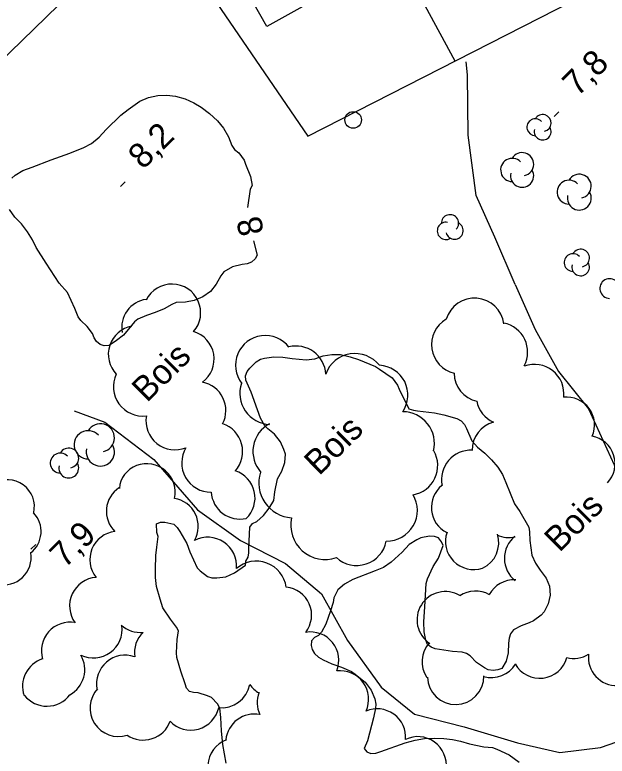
# Model space of a CAD drawing. Extents: x 381879 to 384696, y 5564785 to 5567594.
# Drawn here: x 382944.6 to 383016.3, y 5565699.1 to 5565788.8 of the extents above; entities that cross this region are included whole.
import ezdxf

# ---------------------------------------------------------------- set-up
doc = ezdxf.new("R2010")
doc.units = 0
for name, color, linetype in [('Niveau 2', 7, 'Continuous'), ('Niveau 21', 7, 'Continuous'), ('Niveau 22', 7, 'Continuous'), ('Niveau 3', 7, 'Continuous'), ('Niveau 31', 7, 'Continuous'), ('Niveau 36', 7, 'Continuous'), ('Niveau 41', 7, 'Continuous'), ('Niveau 44', 7, 'Continuous')]:
    doc.layers.add(name, color=color, linetype=linetype)

msp = doc.modelspace()

# ---------------------------------------------------------------- linework, layer by layer
at = {"layer": 'Niveau 2'}
for points in [[(382944.26, 5565769.03), (382944.69, 5565769.41), (382945.61, 5565769.97), (382946.74, 5565770.36), (382949.01, 5565771.25), (382951.29, 5565772.07), (382952.98, 5565772.77), (382953.92, 5565773.25), (382954.82, 5565774.02), (382955.69, 5565774.92), (382957.44, 5565776.67), (382958.34, 5565777.37), (382959.77, 5565778.35), (382960.82, 5565778.79), (382961.91, 5565779.05), (382963.03, 5565779.1), (382964.07, 5565778.96), (382965.22, 5565778.66), (382966.29, 5565778.18), (382967.16, 5565777.65), (382968.19, 5565776.85), (382969.13, 5565775.97), (382969.88, 5565775.09), (382970.47, 5565774.06), (382970.87, 5565772.98), (382971.22, 5565772.52), (382971.71, 5565772.13), (382972.35, 5565771.24), (382972.53, 5565770.73), (382973.12, 5565769.26), (382973.33, 5565768.16), (382973.1, 5565767.71), (382972.79, 5565765.52)], [(382950, 5565756.35), (382948.41, 5565758.77), (382947.21, 5565760.67), (382946.78, 5565761.6), (382946.18, 5565762.57), (382945.43, 5565763.51), (382944.65, 5565764.35), (382943.99, 5565765.27)], [(382973.5, 5565761.48), (382973.93, 5565759.75), (382973.71, 5565759.3), (382973.27, 5565758.9), (382972.72, 5565758.69), (382972.13, 5565758.61), (382970.94, 5565758.34), (382969.91, 5565757.71), (382969.55, 5565757.22), (382968.98, 5565756.22), (382968.3, 5565755.33), (382967.39, 5565754.71), (382966.34, 5565754.24), (382965.27, 5565754.04), (382964.15, 5565753.99), (382963.64, 5565753.78), (382962.68, 5565753.25), (382961.59, 5565752.79), (382960.57, 5565752.44), (382959.53, 5565751.99), (382959.12, 5565751.67), (382958.76, 5565751.23), (382957.78, 5565750.05), (382956.92, 5565749.42), (382956.03, 5565748.8), (382955.43, 5565748.75), (382954.96, 5565748.93), (382954.53, 5565749.29), (382954.21, 5565749.75), (382954.03, 5565750.25), (382953.4, 5565751.1), (382952.6, 5565751.82), (382952.3, 5565752.29), (382951.88, 5565753.3), (382950.99, 5565755.2), (382950, 5565756.35)], [(382961.97, 5565725.69), (382961.82, 5565726.2), (382961.76, 5565727.22), (382962.25, 5565727.45), (382962.78, 5565727.44), (382963.86, 5565727.19), (382964.28, 5565726.79), (382964.58, 5565726.32), (382965.43, 5565724.87), (382965.81, 5565723.84), (382966.67, 5565721.9), (382967.03, 5565721.55), (382967.94, 5565720.88), (382968.47, 5565720.69), (382969.08, 5565720.69), (382970.15, 5565720.83), (382971.19, 5565721.32), (382972.55, 5565722.22), (382972.59, 5565722.73), (382972.84, 5565723.2), (382972.95, 5565723.74), (382972.94, 5565724.29), (382973.04, 5565726.84), (382973.39, 5565727.28), (382973.9, 5565727.54), (382974.72, 5565728.26), (382975.39, 5565729.13), (382975.94, 5565730.07), (382976.09, 5565731.09), (382976.4, 5565732.69), (382976.91, 5565733.62), (382977.27, 5565734.64), (382977.36, 5565735.68), (382977.18, 5565736.23), (382976.77, 5565737.16), (382976.04, 5565738.08), (382975.22, 5565738.71), (382974.86, 5565739.09), (382974.36, 5565740.01), (382974, 5565741.04), (382973.21, 5565743.18), (382972.57, 5565744.62), (382972.54, 5565745.13), (382972.74, 5565745.67), (382973.05, 5565746.07), (382973.82, 5565746.83), (382974.34, 5565747.15), (382974.84, 5565747.29), (382975.95, 5565747.44), (382977.06, 5565747.4), (382978.16, 5565747.24), (382979.86, 5565747.08), (382980.9, 5565747.18), (382981.92, 5565747.54), (382982.97, 5565747.73), (382984, 5565747.72), (382985.2, 5565747.45), (382986.18, 5565747.1), (382988.25, 5565746.28), (382988.73, 5565745.94), (382990.27, 5565744.91), (382990.93, 5565744.01), (382991.11, 5565743.51), (382992.3, 5565741.13), (382992.84, 5565740.97), (382993.34, 5565740.92), (382995.4, 5565740.66), (382996.5, 5565740.42), (382998.1, 5565739.98), (382998.6, 5565739.69)], [(382998.6, 5565739.69), (382999.03, 5565739.26), (382999.24, 5565738.76), (382999.92, 5565737.29), (383000.59, 5565736.52), (383001.47, 5565735.77), (383002.27, 5565734.97), (383003.03, 5565734.08), (383003.6, 5565733.2), (383004.01, 5565732.23), (383005.07, 5565729.66), (383005.7, 5565728.72), (383006.8, 5565726.85), (383006.88, 5565726.29), (383006.9, 5565725.23), (383007.15, 5565723.43), (383007.59, 5565722.48), (383008.17, 5565721.62), (383008.9, 5565720.66), (383009.31, 5565719.68), (383009.39, 5565718.61), (383009.14, 5565717.55), (383008.67, 5565716.59), (383008.27, 5565716.19), (383007.36, 5565715.5), (383006.84, 5565715.26), (383005.86, 5565714.9), (383004.95, 5565714.41), (383004.59, 5565713.92), (383004.41, 5565713.41), (383004.33, 5565712.8), (383004.3, 5565711.62), (383004.07, 5565710.61), (383003.53, 5565709.75), (383003.05, 5565709.57), (383002.5, 5565709.48), (383001.88, 5565709.57), (383001.42, 5565709.82), (383000.45, 5565710.47), (382999.7, 5565711.27), (382999.27, 5565711.54), (382998.74, 5565711.71), (382997.58, 5565711.79), (382995.48, 5565712.1), (382994.99, 5565712.33), (382994.56, 5565712.66), (382994.32, 5565713.17), (382994.14, 5565714.19), (382994.11, 5565715.39), (382994.2, 5565717.18), (382994.36, 5565720.03), (382994.54, 5565720.58), (382995.22, 5565722.09), (382995.88, 5565723.08), (382996.45, 5565724.6), (382996.24, 5565725.07), (382995.86, 5565725.54), (382995.37, 5565725.71), (382994.77, 5565725.75), (382993.75, 5565725.56), (382993.24, 5565725.32), (382992.31, 5565724.72), (382991.47, 5565723.83), (382990.16, 5565722.62), (382989.22, 5565721.96), (382988.21, 5565721.56), (382985.53, 5565720.5), (382984.51, 5565719.95), (382983.7, 5565719.25), (382983.22, 5565718.3), (382983.13, 5565717.74), (382982.81, 5565716.71), (382982.25, 5565715.09), (382981.74, 5565714.13), (382981.34, 5565713.73), (382980.87, 5565713.47), (382980.52, 5565713.1), (382980.47, 5565712.52), (382980.61, 5565712.03), (382980.89, 5565711.57), (382981.35, 5565711.13), (382981.91, 5565710.77), (382982.97, 5565710.29), (382984.16, 5565709.89), (382985.36, 5565709.36), (382985.79, 5565709.05), (382987.01, 5565708.07), (382987.73, 5565707.12), (382988.18, 5565706.06), (382988.3, 5565705.44), (382988.27, 5565704.93), (382988, 5565703.76), (382987.28, 5565701), (382986.87, 5565700.05), (382987.2, 5565699.67), (382987.69, 5565699.44), (382988.31, 5565699.49), (382988.91, 5565699.71), (382991.82, 5565700.75), (382993.03, 5565701.07), (382994.19, 5565701.26)], [(382970.2, 5565698.28), (382969.8, 5565700.53), (382969.61, 5565702.21), (382969.53, 5565703.83), (382969.43, 5565704.94), (382969.16, 5565705.48), (382968.42, 5565706.22), (382967.94, 5565706.42), (382966.8, 5565706.8), (382966.26, 5565706.84), (382965.76, 5565706.97), (382965.41, 5565707.36), (382965.25, 5565707.9), (382964.7, 5565709.42), (382964.21, 5565711.06), (382964.2, 5565711.65), (382964.28, 5565713.25), (382964.44, 5565714.28), (382964.18, 5565714.74), (382963.46, 5565715.7), (382962.55, 5565717.06), (382962.2, 5565718.11), (382961.76, 5565719.64), (382961.65, 5565720.73), (382961.63, 5565721.77), (382961.68, 5565723.39), (382961.81, 5565724.4), (382961.97, 5565725.69)], [(382994.19, 5565701.26), (382995.34, 5565701.31), (382996.53, 5565701.27), (382997.56, 5565701.15), (382998.55, 5565700.95), (382999.64, 5565700.62), (383001.34, 5565700.26), (383002.42, 5565700.18), (383002.92, 5565699.99), (383004.41, 5565699.29), (383005.64, 5565698.42)]]:
    msp.add_lwpolyline(points, dxfattribs=at)
at = {"layer": 'Niveau 21'}
msp.add_lwpolyline([(382914.61, 5565754.3), (382936.73, 5565777.21), (382952.8, 5565792.82), (382963.76, 5565801.52), (382976.97, 5565810.61), (383000.04, 5565824), (383016.43, 5565833.11), (383031.77, 5565840.06), (383045.77, 5565844.63), (383055.95, 5565847.35), (383061.35, 5565847.84), (383065.37, 5565846.21), (383068.45, 5565843.53), (383070.89, 5565839.89)], dxfattribs=at)
at = {"layer": 'Niveau 22'}
for points in [[(383005.14, 5565756.17), (383002.69, 5565761.9), (383000.42, 5565766.95), (382999.46, 5565774.26), (382999.37, 5565781.55), (382999.22, 5565783.11)], [(383005.14, 5565756.17), (383007.58, 5565750.73), (383010.37, 5565745.68), (383014, 5565741.13), (383017.55, 5565733.39), (383021.21, 5565726.5), (383025.43, 5565721.93), (383027.94, 5565717.14), (383028.48, 5565711.52), (383029.32, 5565705.94), (383031.4, 5565700.76), (383032.94, 5565694.87), (383033.8, 5565689.8), (383035.77, 5565686.13), (383037.71, 5565681.07), (383040.42, 5565674.31)], [(382951.83, 5565740.92), (382955.51, 5565739.53), (382961.45, 5565735.01), (382966.72, 5565728.93), (382971.91, 5565725.21), (382977.38, 5565722.44), (382981.72, 5565718.78), (382984.86, 5565713.13), (382988.92, 5565707.48), (382992.95, 5565704.21), (382998.97, 5565702.7), (383005.41, 5565700.75), (383010.56, 5565699.58), (383015.48, 5565700.17), (383021.4, 5565702.26), (383026.37, 5565705.13), (383029.61, 5565709.24), (383032.93, 5565713.08), (383036.81, 5565716), (383040.62, 5565718.42), (383043.54, 5565721.3)]]:
    msp.add_lwpolyline(points, dxfattribs=at)
at = {"layer": 'Niveau 3'}
for p, q in [((383009.87, 5565776.49), (383010.44, 5565777.06)), ((382957.42, 5565768.05), (382957.99, 5565768.62)), ((382946.59, 5565724.17), (382947.16, 5565724.74))]:
    msp.add_line(p, q, dxfattribs=at)
at = {"layer": 'Niveau 31'}
msp.add_lwpolyline([(382971.04, 5565794.61), (382981.13, 5565800.28), (382985.19, 5565793.05), (382975.1, 5565787.38)], close=True, dxfattribs=at)
at = {"layer": 'Niveau 36'}
msp.add_circle((382985.553, 5565776.09), 1, dxfattribs=at)
at = {"layer": 'Niveau 41'}
for points in [[(382997.88, 5565783.22), (382983.61, 5565809.56)], [(382963.3, 5565798.68), (382980.07, 5565774.13), (383042.17, 5565805.84)]]:
    msp.add_lwpolyline(points, dxfattribs=at)
at = {"layer": 'Niveau 44'}
for centre, radius, start, end in [((383008.468, 5565775.714), 1.023, 282.26915, 149.72624), ((383007.589, 5565775.203), 1.023, 44.11535, 269.80394), ((383008.468, 5565774.692), 1.023, 166.93684, 29.62121), ((383005.986, 5565770.738), 1.398, 282.26915, 149.72624), ((383004.783, 5565770.039), 1.398, 44.11535, 269.80394), ((383005.986, 5565769.34), 1.398, 166.93684, 29.62121), ((383012.896, 5565768.083), 1.445, 282.26915, 149.72624), ((383011.654, 5565767.361), 1.445, 44.11535, 269.80394), ((383012.896, 5565766.638), 1.445, 166.93684, 29.62121), ((383013.059, 5565759.38), 1.07, 282.26915, 149.72624), ((383012.139, 5565758.845), 1.07, 44.11535, 269.80394), ((383013.059, 5565758.31), 1.07, 166.93684, 29.62121), ((383016.574, 5565755.7), 1.19, 44.11535, 269.80394), ((383003.085, 5565748.021), 3.566, 332.23791, 78.61323), ((382954.977, 5565737.645), 1.707, 282.26915, 149.72624), ((382968.623, 5565735.975), 3.565, 319.03076, 71.22466), ((382953.51, 5565736.792), 1.707, 44.11535, 269.80394), ((382951.16, 5565735.192), 1.204, 282.26915, 149.72624), ((382954.977, 5565735.938), 1.707, 166.93684, 29.62121), ((382992.228, 5565734.266), 3.552, 279.26271, 30.36342), ((382950.125, 5565734.591), 1.204, 44.11535, 269.80394), ((382951.16, 5565733.989), 1.204, 166.93684, 29.62121), ((382959.12, 5565728.757), 3.414, 123.72138, 225.56115), ((382989.608, 5565728.863), 3.713, 269.10953, 30.7211), ((382985.983, 5565725.829), 3.631, 227.29769, 349.22981), ((382973.827, 5565719.048), 3.673, 8.48236, 130.53076), ((382954.134, 5565714.487), 3.477, 244.23376, 7.46701), ((382949.621, 5565709.612), 3.472, 298.81948, 30.16647), ((383002.265, 5565712.05), 3.406, 254.29453, 328.65221), ((382983.986, 5565706.028), 3.439, 335.29034, 97.11484), ((382948.515, 5565708.65), 3.472, 218.40596, 323.18705)]:
    msp.add_arc(centre, radius, start, end, dxfattribs=at)
for centre, major_axis, ratio, start_param, end_param in [((382997.262, 5565763.587), (0.912, -0.513), 0.999925, 6.029005, 9.968014), ((382996.769, 5565762.67), (0.912, -0.513), 0.999925, 1.88946, 5.776035), ((382997.815, 5565762.706), (0.912, -0.513), 0.999925, 3.902388, 7.872264), ((382963.632, 5565752.767), (-1.545, 3.113), 0.999985, 3.537026, 6.933673), ((382961.033, 5565750.961), (-2.744, -2.124), 0.999985, 4.206476, 5.789984), ((383000.229, 5565750.973), (-3.57, 0.023), 0.999871, 3.274852, 6.005186), ((382998.61, 5565748.925), (-0.823, -3.473), 0.999872, 3.908751, 6.273874), ((382959.408, 5565747.738), (-3.34, 0.945), 0.999408, 5.169945, 7.322225), ((382965.261, 5565747.16), (-1.136, 3.284), 0.999985, 3.445702, 5.659007), ((382974.925, 5565746.414), (1.104, -3.427), 0.999352, 1.908495, 5.055203), ((382978.648, 5565745.149), (-3.267, 1.509), 0.999875, 3.633014, 5.389209), ((382985.772, 5565744.081), (-0.604, 3.709), 0.999624, 5.2197, 7.345321), ((383007.471, 5565742.961), (-2.664, 2.369), 0.999986, 3.749859, 5.788773), ((382988.57, 5565742.816), (-3.594, 0.17), 0.999985, 2.594107, 4.717896), ((382960.114, 5565743.82), (-3.219, -1.511), 0.999892, 5.402374, 7.535196), ((383001.318, 5565745.536), (1.215, -3.35), 0.999986, 4.386078, 5.707066), ((382966.679, 5565740.949), (-1.96, 2.875), 0.999985, 3.636681, 5.497134), ((382975.622, 5565743.049), (-1.659, -3.41), 0.998006, 4.845898, 6.689352), ((383011.378, 5565739.201), (0.496, 3.329), 0.998284, 4.443588, 6.549309), ((383003.981, 5565742.781), (3.532, -0.437), 0.999873, 3.468129, 4.409707), ((382991.526, 5565736.943), (3.668, 1.194), 0.999908, 5.735839, 7.533195), ((382964.005, 5565739.704), (-2.779, -2.151), 0.999931, 5.456956, 7.581965), ((383003.492, 5565736.124), (-2.949, -1.992), 0.999771, 4.396699, 5.688956), ((382977.208, 5565735.996), (1.643, -3.405), 0.999558, 3.176757, 4.996336), ((383013.815, 5565734.495), (3.234, 1.078), 0.998372, 5.216723, 7.345404), ((382968.363, 5565734.608), (-3.282, -1.349), 0.999777, 5.34734, 7.471817), ((382999.788, 5565732.581), (-2.587, -2.449), 0.999773, 3.91135, 5.727609), ((382960.65, 5565731.191), (-3.06, 1.493), 0.969373, 3.340724, 6.649495), ((382970.221, 5565730.359), (-0.55, 3.419), 0.999985, 3.749119, 5.806463), ((382978.365, 5565732.179), (-3.796, -1.84), 0.999376, 5.517838, 7.342273), ((382943.738, 5565729.317), (-3.252, 0.289), 0.999932, 2.995713, 6.523443), ((382998.42, 5565729.218), (0.335, -3.394), 0.999861, 3.719056, 5.71477), ((382971.865, 5565731.288), (-0.838, -3.381), 0.999729, 5.020711, 6.74044), ((382963.468, 5565726.961), (-1.395, 3.105), 0.981128, 3.765533, 5.714086), ((382944.547, 5565726.305), (0.381, 3.243), 0.999932, 3.912805, 5.590641), ((382982.154, 5565727.071), (-2.885, -2.98), 0.998549, 5.262101, 7.388974), ((382957.151, 5565722.905), (-3.194, 1.289), 0.998915, 5.218299, 7.340175), ((383000.126, 5565725.113), (2.61, -2.196), 0.99986, 3.508947, 5.732), ((382967.966, 5565722.136), (1.943, 2.895), 0.999952, 5.218517, 7.346757), ((382999.747, 5565724.948), (0.621, 3.354), 0.999861, 3.766224, 5.207045), ((383004.414, 5565728.994), (2.36, -2.474), 0.99986, 5.079269, 5.738691), ((383007.257, 5565723.068), (0.153, -3.415), 0.99986, 3.779965, 5.571203), ((382943.343, 5565723.134), (2.374, 2.246), 0.999932, 3.710323, 5.705773), ((382954.731, 5565717.298), (-1.394, -3.181), 0.999866, 3.632957, 5.751479), ((383005.008, 5565717.054), (-3.325, 0.766), 0.999938, 4.881391, 6.015446), ((382977.116, 5565716.199), (3.135, 1.339), 0.999949, 5.219872, 7.349182), ((382996.688, 5565715.627), (-3.25, 1.047), 0.999718, 4.483043, 7.582815), ((383000.329, 5565715.702), (-3.333, -0.727), 0.999984, 3.978853, 5.085472), ((382951.318, 5565711.876), (-2.642, -2.261), 0.999985, 3.829429, 5.864398), ((382959.823, 5565717.577), (-0.424, -3.458), 0.999799, 5.671228, 6.500889), ((382962.562, 5565711.621), (-2.8, -2.041), 0.999985, 4.850299, 5.79257), ((382980.389, 5565710.735), (2.895, 1.832), 0.999683, 5.331078, 7.45985), ((382997.302, 5565710.58), (-0.366, -3.402), 0.999938, 4.092016, 5.414783), ((382949.046, 5565707.584), (-0.723, -3.401), 0.999866, 3.661873, 5.245376), ((382957.989, 5565707.884), (-3.264, 1.183), 0.999863, 4.731236, 6.805913), ((383008.114, 5565711.972), (3.148, 1.31), 0.999938, 3.260095, 5.618044), ((383012.219, 5565714.375), (3.413, -0.142), 0.999984, 4.503619, 5.308794), ((383017.402, 5565711.085), (2.537, -2.276), 0.99986, 3.758046, 5.477793), ((382997.945, 5565708.798), (3.276, 0.971), 0.999985, 2.881785, 6.007199), ((382957.205, 5565704.976), (-3.186, -1.399), 0.995024, 5.136393, 7.741258), ((382969.645, 5565708.465), (3.116, -1.549), 0.999518, 5.060313, 6.550557), ((382975.898, 5565709.781), (2.269, -2.624), 0.999587, 4.610198, 5.039978), ((382977.407, 5565705.592), (-3.081, 1.592), 0.998858, 0.113157, 0.903113), ((382965.91, 5565705.767), (3.281, 1.141), 0.99994, 3.570956, 5.725248), ((382988.533, 5565701.521), (-2.699, 2.073), 0.973496, 3.695764, 5.790538), ((382973.606, 5565700.766), (-2.59, 2.306), 0.998858, 5.247935, 6.911771), ((382960.173, 5565704.568), (1.082, 3.307), 0.999501, 2.861328, 4.672039), ((382971.356, 5565697.911), (-3.329, 0.617), 0.99573, 5.229719, 7.60693), ((382993.479, 5565698.127), (-2.043, 2.73), 0.968832, 3.923364, 6.121158)]:
    msp.add_ellipse(centre, major_axis=major_axis, ratio=ratio, start_param=start_param, end_param=end_param, dxfattribs=at)

# ---------------------------------------------------------------- texts
at = {"layer": 'Niveau 2'}
msp.add_text('8', height=3, rotation=104.62947, dxfattribs=at).set_placement((382974.82, 5565762.51))
at = {"layer": 'Niveau 3'}
for s, p in [('7,8', (383012.68, 5565778.81)), ('8,2', (382960.15, 5565770)), ('7,9', (382950.68, 5565721.77))]:
    msp.add_text(s, height=3, rotation=44.7717, dxfattribs=at).set_placement(p)
at = {"layer": 'Niveau 44'}
for p in [(382960.6, 5565741.81), (382981.44, 5565732.97), (383010.49, 5565723.69)]:
    msp.add_text('Bois', height=2.9999, rotation=44.77074, dxfattribs=at).set_placement(p)

doc.saveas('drawing.dxf')
